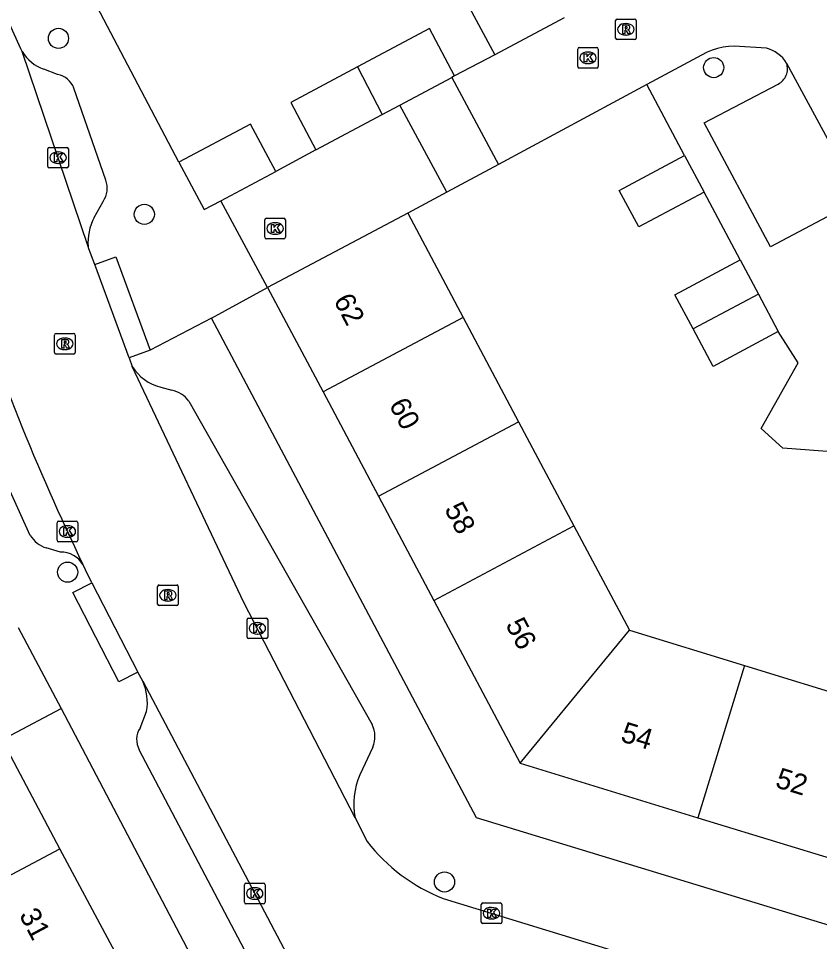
# Model space of a CAD drawing. Extents: x 160304 to 160954, y 383686 to 384161.
# Drawn here: x 160687.46 to 160726.4, y 383852.63 to 383897.47 of the extents above; entities that cross this region are included whole.
import ezdxf

# ---------------------------------------------------------------- set-up
doc = ezdxf.new("R2010")
doc.units = 0
for name, color, linetype in [('IMGEO_Boom', 7, 'Continuous'), ('IMGEO_Kolk', 7, 'Continuous'), ('IMGEO_Pand', 7, 'Continuous'), ('IMGEO_Pand_nummerreeks', 7, 'Continuous'), ('IMGEO_Rijbaan_lokaal_open', 7, 'Continuous'), ('IMGEO_Rioolput', 7, 'Continuous'), ('IMGEO_Voetpad_open', 7, 'Continuous')]:
    doc.layers.add(name, color=color, linetype=linetype)

msp = doc.modelspace()

# ---------------------------------------------------------------- linework, layer by layer
at = {"layer": 'IMGEO_Boom'}
for centre in [(160689.405, 383896.502), (160721.252, 383895.082), (160693.579, 383887.955), (160689.851, 383870.576), (160708.169, 383855.527)]:
    msp.add_circle(centre, 0.489, dxfattribs=at)
at = {"layer": 'IMGEO_Kolk'}
for p, q in [((160714.641, 383895.131), (160714.641, 383895.983)), ((160714.716, 383896.057), (160715.568, 383896.057)), ((160715.129, 383895.837), (160715.154, 383895.837)), ((160715.642, 383895.983), (160715.642, 383895.131)), ((160715.152, 383895.277), (160715.127, 383895.277)), ((160715.568, 383895.057), (160714.716, 383895.057)), ((160688.888, 383890.28), (160688.888, 383891.132)), ((160688.963, 383891.206), (160689.815, 383891.206)), ((160689.376, 383890.986), (160689.401, 383890.986)), ((160689.889, 383891.132), (160689.889, 383890.28)), ((160689.399, 383890.426), (160689.374, 383890.426)), ((160689.815, 383890.206), (160688.963, 383890.206)), ((160699.437, 383886.84), (160699.437, 383887.692)), ((160699.512, 383887.766), (160700.364, 383887.766)), ((160700.438, 383887.692), (160700.438, 383886.84)), ((160699.925, 383887.546), (160699.95, 383887.546)), ((160700.364, 383886.766), (160699.512, 383886.766)), ((160699.948, 383886.986), (160699.923, 383886.986)), ((160689.34, 383872.124), (160689.34, 383872.976)), ((160689.415, 383873.05), (160690.267, 383873.05)), ((160689.828, 383872.83), (160689.853, 383872.83)), ((160690.341, 383872.976), (160690.341, 383872.124)), ((160690.267, 383872.05), (160689.415, 383872.05)), ((160689.851, 383872.27), (160689.826, 383872.27)), ((160698.649, 383868.346), (160699.501, 383868.346)), ((160698.574, 383867.42), (160698.574, 383868.272)), ((160699.062, 383868.126), (160699.087, 383868.126)), ((160699.575, 383868.272), (160699.575, 383867.42)), ((160699.085, 383867.566), (160699.06, 383867.566)), ((160699.501, 383867.346), (160698.649, 383867.346)), ((160698.445, 383854.541), (160698.445, 383855.393)), ((160698.52, 383855.467), (160699.372, 383855.467)), ((160699.446, 383855.393), (160699.446, 383854.541)), ((160698.933, 383855.247), (160698.958, 383855.247)), ((160699.372, 383854.467), (160698.52, 383854.467)), ((160698.956, 383854.687), (160698.931, 383854.687)), ((160710.028, 383854.509), (160710.88, 383854.509)), ((160709.953, 383853.583), (160709.953, 383854.435)), ((160710.441, 383854.289), (160710.466, 383854.289)), ((160710.954, 383854.435), (160710.954, 383853.583)), ((160710.464, 383853.729), (160710.439, 383853.729)), ((160710.88, 383853.509), (160710.028, 383853.509))]:
    msp.add_line(p, q, dxfattribs=at)
for points in [[(160714.641, 383895.131), (160714.641, 383895.983)], [(160714.716, 383896.057), (160715.568, 383896.057)], [(160714.962, 383895.757), (160715.085, 383895.757), (160715.085, 383895.606), (160715.215, 383895.757), (160715.379, 383895.757), (160715.233, 383895.606), (160715.386, 383895.357), (160715.234, 383895.357), (160715.149, 383895.521), (160715.085, 383895.454), (160715.085, 383895.357), (160714.962, 383895.357), (160714.962, 383895.757)], [(160715.642, 383895.983), (160715.642, 383895.131)], [(160715.568, 383895.057), (160714.716, 383895.057)], [(160688.888, 383890.28), (160688.888, 383891.132)], [(160688.963, 383891.206), (160689.815, 383891.206)], [(160689.209, 383890.906), (160689.332, 383890.906), (160689.332, 383890.755), (160689.462, 383890.906), (160689.626, 383890.906), (160689.48, 383890.755), (160689.633, 383890.506), (160689.481, 383890.506), (160689.396, 383890.67), (160689.332, 383890.603), (160689.332, 383890.506), (160689.209, 383890.506), (160689.209, 383890.906)], [(160689.889, 383891.132), (160689.889, 383890.28)], [(160689.815, 383890.206), (160688.963, 383890.206)], [(160699.437, 383886.84), (160699.437, 383887.692)], [(160699.512, 383887.766), (160700.364, 383887.766)], [(160700.438, 383887.692), (160700.438, 383886.84)], [(160699.758, 383887.466), (160699.881, 383887.466), (160699.881, 383887.315), (160700.011, 383887.466), (160700.175, 383887.466), (160700.029, 383887.315), (160700.182, 383887.066), (160700.03, 383887.066), (160699.945, 383887.23), (160699.881, 383887.163), (160699.881, 383887.066), (160699.758, 383887.066), (160699.758, 383887.466)], [(160700.364, 383886.766), (160699.512, 383886.766)], [(160689.34, 383872.124), (160689.34, 383872.976)], [(160689.415, 383873.05), (160690.267, 383873.05)], [(160690.341, 383872.976), (160690.341, 383872.124)], [(160689.661, 383872.75), (160689.784, 383872.75), (160689.784, 383872.599), (160689.914, 383872.75), (160690.078, 383872.75), (160689.932, 383872.599), (160690.085, 383872.35), (160689.933, 383872.35), (160689.848, 383872.514), (160689.784, 383872.447), (160689.784, 383872.35), (160689.661, 383872.35), (160689.661, 383872.75)], [(160690.267, 383872.05), (160689.415, 383872.05)], [(160698.649, 383868.346), (160699.501, 383868.346)], [(160698.574, 383867.42), (160698.574, 383868.272)], [(160698.895, 383868.046), (160699.018, 383868.046), (160699.018, 383867.895), (160699.148, 383868.046), (160699.312, 383868.046), (160699.166, 383867.895), (160699.319, 383867.646), (160699.167, 383867.646), (160699.082, 383867.81), (160699.018, 383867.743), (160699.018, 383867.646), (160698.895, 383867.646), (160698.895, 383868.046)], [(160699.575, 383868.272), (160699.575, 383867.42)], [(160699.501, 383867.346), (160698.649, 383867.346)], [(160698.445, 383854.541), (160698.445, 383855.393)], [(160698.52, 383855.467), (160699.372, 383855.467)], [(160699.446, 383855.393), (160699.446, 383854.541)], [(160698.766, 383855.167), (160698.889, 383855.167), (160698.889, 383855.016), (160699.019, 383855.167), (160699.183, 383855.167), (160699.037, 383855.016), (160699.19, 383854.767), (160699.038, 383854.767), (160698.953, 383854.931), (160698.889, 383854.864), (160698.889, 383854.767), (160698.766, 383854.767), (160698.766, 383855.167)], [(160699.372, 383854.467), (160698.52, 383854.467)], [(160710.028, 383854.509), (160710.88, 383854.509)], [(160709.953, 383853.583), (160709.953, 383854.435)], [(160710.274, 383854.209), (160710.397, 383854.209), (160710.397, 383854.058), (160710.527, 383854.209), (160710.691, 383854.209), (160710.545, 383854.058), (160710.698, 383853.809), (160710.546, 383853.809), (160710.461, 383853.973), (160710.397, 383853.906), (160710.397, 383853.809), (160710.274, 383853.809), (160710.274, 383854.209)], [(160710.954, 383854.435), (160710.954, 383853.583)], [(160710.88, 383853.509), (160710.028, 383853.509)]]:
    msp.add_lwpolyline(points, dxfattribs=at)
for centre, start, end in [((160714.718, 383895.981), 91.552, 178.448), ((160714.718, 383895.981), 91.552, 178.448), ((160715.566, 383895.981), 1.552, 88.448), ((160715.566, 383895.981), 1.552, 88.448), ((160714.718, 383895.133), 181.552, 268.448), ((160714.718, 383895.133), 181.552, 268.448), ((160715.566, 383895.133), 271.552, 358.448), ((160715.566, 383895.133), 271.552, 358.448), ((160688.965, 383891.13), 91.552, 178.448), ((160688.965, 383891.13), 91.552, 178.448), ((160689.813, 383891.13), 1.552, 88.448), ((160689.813, 383891.13), 1.552, 88.448), ((160688.965, 383890.282), 181.552, 268.448), ((160688.965, 383890.282), 181.552, 268.448), ((160689.813, 383890.282), 271.552, 358.448), ((160689.813, 383890.282), 271.552, 358.448), ((160699.514, 383887.69), 91.552, 178.448), ((160699.514, 383887.69), 91.552, 178.448), ((160700.362, 383887.69), 1.552, 88.448), ((160700.362, 383887.69), 1.552, 88.448), ((160699.514, 383886.842), 181.552, 268.448), ((160699.514, 383886.842), 181.552, 268.448), ((160700.362, 383886.842), 271.552, 358.448), ((160700.362, 383886.842), 271.552, 358.448), ((160689.417, 383872.974), 91.552, 178.448), ((160689.417, 383872.974), 91.552, 178.448), ((160690.265, 383872.974), 1.552, 88.448), ((160690.265, 383872.974), 1.552, 88.448), ((160689.417, 383872.126), 181.552, 268.448), ((160689.417, 383872.126), 181.552, 268.448), ((160690.265, 383872.126), 271.552, 358.448), ((160690.265, 383872.126), 271.552, 358.448), ((160698.651, 383868.27), 91.552, 178.448), ((160698.651, 383868.27), 91.552, 178.448), ((160699.499, 383868.27), 1.552, 88.448), ((160699.499, 383868.27), 1.552, 88.448), ((160698.651, 383867.422), 181.552, 268.448), ((160698.651, 383867.422), 181.552, 268.448), ((160699.499, 383867.422), 271.552, 358.448), ((160699.499, 383867.422), 271.552, 358.448), ((160698.522, 383855.391), 91.552, 178.448), ((160698.522, 383855.391), 91.552, 178.448), ((160699.37, 383855.391), 1.552, 88.448), ((160699.37, 383855.391), 1.552, 88.448), ((160698.522, 383854.543), 181.552, 268.448), ((160698.522, 383854.543), 181.552, 268.448), ((160699.37, 383854.543), 271.552, 358.448), ((160699.37, 383854.543), 271.552, 358.448), ((160710.03, 383854.433), 91.552, 178.448), ((160710.03, 383854.433), 91.552, 178.448), ((160710.878, 383854.433), 1.552, 88.448), ((160710.878, 383854.433), 1.552, 88.448), ((160710.03, 383853.585), 181.552, 268.448), ((160710.03, 383853.585), 181.552, 268.448), ((160710.878, 383853.585), 271.552, 358.448), ((160710.878, 383853.585), 271.552, 358.448)]:
    msp.add_arc(centre, 0.0765, start, end, dxfattribs=at)
for centre, major_axis, ratio, start_param, end_param in [((160715.128, 383895.557), (-0.387, 0.002), 0.722429, 4.712389, 7.853982), ((160715.153, 383895.557), (-0.39, 0.002), 0.717154, 1.570796, 4.712389), ((160689.375, 383890.706), (-0.387, 0.002), 0.722429, 4.712389, 7.853982), ((160689.4, 383890.706), (-0.39, 0.002), 0.717154, 1.570796, 4.712389), ((160699.924, 383887.266), (-0.387, 0.002), 0.722429, 4.712389, 7.853982), ((160699.949, 383887.266), (-0.39, 0.002), 0.717154, 1.570796, 4.712389), ((160689.827, 383872.55), (-0.387, 0.002), 0.722429, 4.712389, 7.853982), ((160689.852, 383872.55), (-0.39, 0.002), 0.717154, 1.570796, 4.712389), ((160699.061, 383867.846), (-0.387, 0.002), 0.722429, 4.712389, 7.853982), ((160699.086, 383867.846), (-0.39, 0.002), 0.717154, 1.570796, 4.712389), ((160698.932, 383854.967), (-0.387, 0.002), 0.722429, 4.712389, 7.853982), ((160698.957, 383854.967), (-0.39, 0.002), 0.717154, 1.570796, 4.712389), ((160710.44, 383854.009), (-0.387, 0.002), 0.722429, 4.712389, 7.853982), ((160710.465, 383854.009), (-0.39, 0.002), 0.717154, 1.570796, 4.712389)]:
    msp.add_ellipse(centre, major_axis=major_axis, ratio=ratio, start_param=start_param, end_param=end_param, dxfattribs=at)
at = {"layer": 'IMGEO_Pand'}
for points in [[(160712.748, 383899.815), (160709.375, 383898.014), (160710.608, 383895.703)], [(160713.982, 383897.495), (160710.608, 383895.703)], [(160708.662, 383894.677), (160707.434, 383896.978), (160703.947, 383895.116)], [(160703.947, 383895.116), (160700.695, 383893.38), (160701.916, 383891.092)], [(160703.947, 383895.116), (160705.135, 383892.802)], [(160706, 383893.262), (160708.517, 383894.6)], [(160708.662, 383894.677), (160708.517, 383894.6)], [(160705.135, 383892.802), (160706, 383893.262)], [(160701.916, 383891.092), (160705.135, 383892.802)], [(160699.973, 383890.038), (160698.745, 383892.339), (160695.264, 383890.492)], [(160720.784, 383889.036), (160717.607, 383887.342), (160716.661, 383889.115), (160719.838, 383890.809)], [(160719.838, 383890.809), (160720.784, 383889.036)], [(160695.264, 383890.492), (160696.493, 383888.189), (160697.29, 383888.613)], [(160697.29, 383888.613), (160699.973, 383890.038)], [(160706.386, 383888.016), (160699.572, 383884.396)], [(160706.386, 383888.016), (160709.078, 383882.95)], [(160720.248, 383882.389), (160719.362, 383884.05), (160722.539, 383885.745)], [(160722.539, 383885.745), (160723.428, 383884.078)], [(160699.572, 383884.396), (160702.264, 383879.33)], [(160723.428, 383884.078), (160720.248, 383882.389)], [(160723.428, 383884.078), (160724.393, 383882.268)], [(160709.078, 383882.95), (160702.264, 383879.33)], [(160709.078, 383882.95), (160711.769, 383877.884)], [(160724.393, 383882.268), (160721.645, 383880.791), (160721.222, 383880.564), (160720.248, 383882.389)], [(160702.264, 383879.33), (160704.955, 383874.264)], [(160704.955, 383874.264), (160711.769, 383877.884)], [(160711.769, 383877.884), (160714.461, 383872.819)], [(160704.955, 383874.264), (160707.647, 383869.198)], [(160707.647, 383869.198), (160714.461, 383872.819)], [(160714.461, 383872.819), (160717.152, 383867.753)], [(160707.647, 383869.198), (160711.848, 383861.291)], [(160711.848, 383861.291), (160717.152, 383867.753)], [(160717.152, 383867.753), (160722.743, 383866.042)], [(160722.743, 383866.042), (160720.48, 383858.649)], [(160722.743, 383866.042), (160728.334, 383864.331)], [(160689.481, 383857.138), (160686.663, 383862.43)], [(160711.848, 383861.291), (160720.48, 383858.649)], [(160720.48, 383858.649), (160729.196, 383855.981)], [(160682.541, 383853.456), (160689.481, 383857.138)], [(160692.156, 383852.115), (160689.481, 383857.138)]]:
    msp.add_lwpolyline(points, dxfattribs=at)
at = {"layer": 'IMGEO_Rijbaan_lokaal_open'}
for points in [[(160687.649, 383895.859), (160687.584, 383895.992), (160683.512, 383904.948), (160681.85, 383908.464), (160680.633, 383910.769)], [(160724.791, 383895.296), (160728.262, 383888.908), (160752.994, 383901.988)], [(160690.85, 383886.385), (160687.649, 383895.859)], [(160710.608, 383895.703), (160708.662, 383894.677)], [(160724.791, 383895.296), (160724.717, 383895.433), (160724.613, 383895.55), (160724.498, 383895.658), (160724.375, 383895.755), (160724.243, 383895.84), (160724.104, 383895.914), (160723.959, 383895.975), (160723.817, 383896.02), (160722.243, 383896.126), (160721.973, 383896.113), (160721.705, 383896.077), (160721.441, 383896.016), (160721.184, 383895.932), (160720.935, 383895.826), (160720.909, 383895.813), (160717.997, 383894.261)], [(160708.517, 383894.6), (160710.785, 383890.382)], [(160717.997, 383894.261), (160710.785, 383890.382)], [(160708.275, 383889.032), (160706, 383893.262)], [(160701.916, 383891.092), (160699.973, 383890.038)], [(160710.785, 383890.382), (160708.275, 383889.032)], [(160708.275, 383889.032), (160706.386, 383888.016)], [(160699.572, 383884.396), (160697.29, 383888.613)], [(160691.168, 383885.513), (160690.888, 383886.273), (160690.85, 383886.385)], [(160692.837, 383880.981), (160691.168, 383885.513)], [(160692.837, 383880.981), (160692.989, 383880.566)], [(160703.825, 383858.637), (160698.422, 383869.109), (160692.989, 383880.566)], [(160691.029, 383870.06), (160690.719, 383870.695), (160690.661, 383870.827), (160690.596, 383870.951)], [(160691.029, 383870.06), (160693.268, 383865.723)], [(160687.448, 383867.888), (160689.542, 383863.958)], [(160693.499, 383865.285), (160693.268, 383865.723)], [(160693.499, 383865.285), (160701.279, 383850.551)], [(160687.096, 383862.66), (160689.542, 383863.958)], [(160703.825, 383858.637), (160704.413, 383857.498)], [(160708.098, 383854.731), (160725.199, 383849.489)]]:
    msp.add_lwpolyline(points, dxfattribs=at)
for centre, radius, start, end in [((160798.565, 383922.838), 119.79, 198.23512, 205.6678), ((160711.209, 383862.712), 8.566, 217.494, 248.7016)]:
    msp.add_arc(centre, radius, start, end, dxfattribs=at)
at = {"layer": 'IMGEO_Rioolput'}
for p, q in [((160716.481, 383896.516), (160716.481, 383897.368)), ((160716.556, 383897.442), (160717.408, 383897.442)), ((160716.969, 383897.222), (160716.994, 383897.222)), ((160717.482, 383897.368), (160717.482, 383896.516)), ((160716.992, 383896.662), (160716.967, 383896.662)), ((160717.408, 383896.442), (160716.556, 383896.442)), ((160689.215, 383881.241), (160689.215, 383882.093)), ((160689.29, 383882.167), (160690.142, 383882.167)), ((160689.703, 383881.947), (160689.728, 383881.947)), ((160690.216, 383882.093), (160690.216, 383881.241)), ((160689.726, 383881.387), (160689.701, 383881.387)), ((160690.142, 383881.167), (160689.29, 383881.167)), ((160694.225, 383869.025), (160694.225, 383869.877)), ((160694.3, 383869.951), (160695.152, 383869.951)), ((160694.713, 383869.731), (160694.738, 383869.731)), ((160695.226, 383869.877), (160695.226, 383869.025)), ((160695.152, 383868.951), (160694.3, 383868.951)), ((160694.736, 383869.171), (160694.711, 383869.171))]:
    msp.add_line(p, q, dxfattribs=at)
for points in [[(160716.481, 383896.516), (160716.481, 383897.368)], [(160716.556, 383897.442), (160717.408, 383897.442)], [(160717.07, 383897.14), (160716.818, 383897.142), (160716.818, 383896.742)], [(160716.996, 383897.061), (160716.942, 383897.061), (160716.942, 383896.98)], [(160717.482, 383897.368), (160717.482, 383896.516)], [(160716.818, 383896.742), (160716.942, 383896.742), (160716.942, 383896.904), (160716.953, 383896.904)], [(160716.942, 383896.98), (160716.994, 383896.98)], [(160717, 383896.875), (160717.071, 383896.742), (160717.211, 383896.742), (160717.146, 383896.868)], [(160717.408, 383896.442), (160716.556, 383896.442)], [(160689.215, 383881.241), (160689.215, 383882.093)], [(160689.29, 383882.167), (160690.142, 383882.167)], [(160689.804, 383881.865), (160689.552, 383881.867), (160689.552, 383881.467)], [(160690.216, 383882.093), (160690.216, 383881.241)], [(160689.552, 383881.467), (160689.676, 383881.467), (160689.676, 383881.629), (160689.687, 383881.629)], [(160689.73, 383881.786), (160689.676, 383881.786), (160689.676, 383881.705)], [(160689.676, 383881.705), (160689.728, 383881.705)], [(160689.734, 383881.6), (160689.805, 383881.467), (160689.945, 383881.467), (160689.88, 383881.593)], [(160690.142, 383881.167), (160689.29, 383881.167)], [(160694.225, 383869.025), (160694.225, 383869.877)], [(160694.3, 383869.951), (160695.152, 383869.951)], [(160695.226, 383869.877), (160695.226, 383869.025)], [(160694.814, 383869.649), (160694.562, 383869.651), (160694.562, 383869.251)], [(160694.562, 383869.251), (160694.686, 383869.251), (160694.686, 383869.413), (160694.697, 383869.413)], [(160694.74, 383869.57), (160694.686, 383869.57), (160694.686, 383869.489)], [(160694.686, 383869.489), (160694.738, 383869.489)], [(160694.744, 383869.384), (160694.815, 383869.251), (160694.955, 383869.251), (160694.89, 383869.377)], [(160695.152, 383868.951), (160694.3, 383868.951)]]:
    msp.add_lwpolyline(points, dxfattribs=at)
for centre, radius, start, end in [((160716.558, 383897.366), 0.0765, 91.552, 178.448), ((160716.558, 383897.366), 0.0765, 91.552, 178.448), ((160717.002, 383896.965), 0.0964, 77.0061, 93.1865), ((160717.016, 383897.022), 0.0378, 276.6634, 79.6772), ((160717.069, 383897.03), 0.109, 350.3612, 89.416), ((160717.406, 383897.366), 0.0765, 1.552, 88.448), ((160717.406, 383897.366), 0.0765, 1.552, 88.448), ((160716.952, 383896.851), 0.0533, 26.0293, 88.6989), ((160716.978, 383897.169), 0.19, 274.7715, 282.9687), ((160717.067, 383897.03), 0.112, 277.5842, 350.9817), ((160717.051, 383896.815), 0.108, 29.5134, 73.7905), ((160716.558, 383896.518), 0.0765, 181.552, 268.448), ((160716.558, 383896.518), 0.0765, 181.552, 268.448), ((160717.406, 383896.518), 0.0765, 271.552, 358.448), ((160717.406, 383896.518), 0.0765, 271.552, 358.448), ((160689.292, 383882.091), 0.0765, 91.552, 178.448), ((160689.292, 383882.091), 0.0765, 91.552, 178.448), ((160689.803, 383881.755), 0.109, 350.3612, 89.416), ((160690.14, 383882.091), 0.0765, 1.552, 88.448), ((160690.14, 383882.091), 0.0765, 1.552, 88.448), ((160689.686, 383881.576), 0.0533, 26.0293, 88.6989), ((160689.712, 383881.894), 0.19, 274.7715, 282.9687), ((160689.736, 383881.69), 0.0964, 77.0061, 93.1865), ((160689.75, 383881.747), 0.0378, 276.6634, 79.6772), ((160689.801, 383881.755), 0.112, 277.5842, 350.9817), ((160689.785, 383881.54), 0.108, 29.5134, 73.7905), ((160689.292, 383881.243), 0.0765, 181.552, 268.448), ((160689.292, 383881.243), 0.0765, 181.552, 268.448), ((160690.14, 383881.243), 0.0765, 271.552, 358.448), ((160690.14, 383881.243), 0.0765, 271.552, 358.448), ((160694.302, 383869.875), 0.0765, 91.552, 178.448), ((160694.302, 383869.875), 0.0765, 91.552, 178.448), ((160695.15, 383869.875), 0.0765, 1.552, 88.448), ((160695.15, 383869.875), 0.0765, 1.552, 88.448), ((160694.696, 383869.36), 0.0533, 26.0293, 88.6989), ((160694.722, 383869.678), 0.19, 274.7715, 282.9687), ((160694.746, 383869.474), 0.0964, 77.0061, 93.1865), ((160694.76, 383869.531), 0.0378, 276.6634, 79.6772), ((160694.813, 383869.539), 0.109, 350.3612, 89.416), ((160694.811, 383869.539), 0.112, 277.5842, 350.9817), ((160694.795, 383869.324), 0.108, 29.5134, 73.7905), ((160694.302, 383869.027), 0.0765, 181.552, 268.448), ((160694.302, 383869.027), 0.0765, 181.552, 268.448), ((160695.15, 383869.027), 0.0765, 271.552, 358.448), ((160695.15, 383869.027), 0.0765, 271.552, 358.448)]:
    msp.add_arc(centre, radius, start, end, dxfattribs=at)
for centre, major_axis, ratio, start_param, end_param in [((160716.968, 383896.942), (-0.387, 0.002), 0.722429, 4.712389, 7.853982), ((160716.993, 383896.942), (-0.39, 0.002), 0.717154, 1.570796, 4.712389), ((160689.702, 383881.667), (-0.387, 0.002), 0.722429, 4.712389, 7.853982), ((160689.727, 383881.667), (-0.39, 0.002), 0.717154, 1.570796, 4.712389), ((160694.712, 383869.451), (-0.387, 0.002), 0.722429, 4.712389, 7.853982), ((160694.737, 383869.451), (-0.39, 0.002), 0.717154, 1.570796, 4.712389)]:
    msp.add_ellipse(centre, major_axis=major_axis, ratio=ratio, start_param=start_param, end_param=end_param, dxfattribs=at)
at = {"layer": 'IMGEO_Voetpad_open'}
for points in [[(160695.264, 383890.492), (160690.46, 383899.614)], [(160727.589, 383888.263), (160724.006, 383886.374), (160720.787, 383892.406), (160724.382, 383894.282), (160724.447, 383894.318), (160724.508, 383894.36), (160724.565, 383894.407), (160724.617, 383894.459), (160724.665, 383894.515), (160724.708, 383894.576), (160724.745, 383894.64), (160724.776, 383894.707), (160724.801, 383894.776), (160724.82, 383894.848), (160724.832, 383894.921), (160724.838, 383894.995), (160724.837, 383895.069), (160724.829, 383895.142), (160724.815, 383895.215), (160724.794, 383895.286), (160724.791, 383895.296)], [(160689.366, 383894.741), (160688.693, 383895.008)], [(160691.71, 383889.611), (160690.152, 383894.08)], [(160719.838, 383890.809), (160717.997, 383894.261)], [(160688.037, 383872.362), (160686.605, 383875.512), (160685.604, 383877.988), (160683.325, 383884.133), (160680.02, 383893.885)], [(160722.539, 383885.745), (160720.784, 383889.036)], [(160691.149, 383887.796), (160691.582, 383888.583)], [(160691.168, 383885.513), (160692.191, 383885.89), (160693.86, 383881.358)], [(160783.419, 383884.791), (160784.889, 383882.06), (160729.382, 383852.644), (160709.724, 383858.649), (160696.844, 383882.915)], [(160696.844, 383882.915), (160699.572, 383884.396)], [(160696.844, 383882.915), (160693.86, 383881.358)], [(160729.61, 383882.099), (160727.471, 383880.781), (160728.564, 383876.473), (160727.418, 383876.385), (160724.609, 383876.602), (160723.561, 383877.56), (160725.363, 383880.737), (160724.393, 383882.268)], [(160693.86, 383881.358), (160692.837, 383880.981)], [(160694.379, 383879.555), (160694.912, 383879.415)], [(160695.75, 383878.881), (160704.648, 383863.172)], [(160689.509, 383871.549), (160688.811, 383871.752)], [(160693.268, 383865.723), (160692.344, 383865.246), (160690.106, 383869.583), (160691.029, 383870.06)], [(160689.542, 383863.958), (160696.833, 383850.07), (160698.822, 383848.768), (160706.29, 383834.575)], [(160693.373, 383863.003), (160693.691, 383863.815)], [(160704.685, 383862.08), (160704.049, 383860.735)], [(160698.606, 383851.929), (160693.334, 383861.949)]]:
    msp.add_lwpolyline(points, dxfattribs=at)
for centre, radius, start, end in [((160689.308, 383896.828), 1.921, 210.2957, 251.335), ((160689.224, 383893.774), 0.977, 18.2275, 81.647), ((160690.642, 383889.222), 1.136, 325.7874, 20.0174), ((160693.305, 383886.602), 2.465, 151.0211, 185.0502), ((160694.963, 383881.82), 2.339, 212.4108, 255.5295), ((160694.61, 383878.017), 1.431, 37.1718, 77.815), ((160689.227, 383873.076), 1.388, 210.9597, 252.556), ((160689.515, 383870.273), 1.276, 32.1017, 90.2645), ((160691.262, 383864.245), 2.467, 349.9561, 24.9267), ((160694.228, 383862.444), 1.022, 146.8134, 208.9484), ((160703.49, 383862.586), 1.298, 337.0503, 26.8309), ((160707.434, 383859.313), 3.672, 157.2072, 190.6042)]:
    msp.add_arc(centre, radius, start, end, dxfattribs=at)

# ---------------------------------------------------------------- texts
at = {"layer": 'IMGEO_Pand_nummerreeks'}
for s, rotation, p in [('62', 297.9826, (160702.755, 383883.778)), ('60', 297.9826, (160705.448, 383878.707)), ('58', 297.9826, (160708.14, 383873.641)), ('56', 297.9815, (160711.112, 383868.028)), ('54', 342.9813, (160716.679, 383862.373)), ('52', 342.9813, (160724.197, 383860.145)), ('31', 298.0374, (160687.476, 383853.925))]:
    msp.add_text(s, height=1, rotation=rotation, dxfattribs=at).set_placement(p)

doc.saveas('drawing.dxf')
